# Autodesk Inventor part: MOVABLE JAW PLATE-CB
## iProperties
Created: 2006-07
Part Number: MOVABLE JAW PLATE-CB
Material: Steel, Mild
Document SubType Name: Modeling
Designer: rollin42
Density: 7.86 g/cm^3
Stock Number: MOVABLE JAW PLATE-CB
Author: rollin42
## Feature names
1. Extrusion1
2. Hole1
3. Rectangular Pattern1
